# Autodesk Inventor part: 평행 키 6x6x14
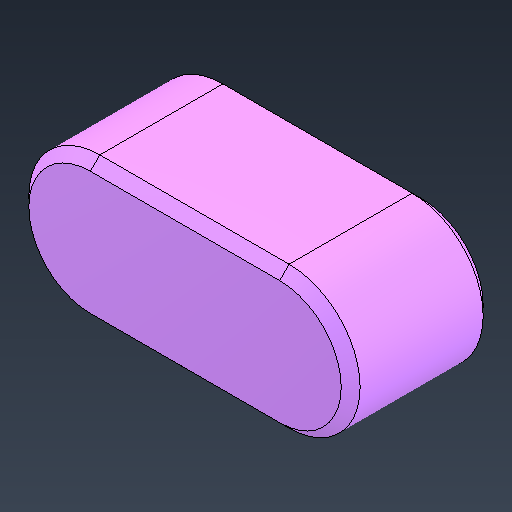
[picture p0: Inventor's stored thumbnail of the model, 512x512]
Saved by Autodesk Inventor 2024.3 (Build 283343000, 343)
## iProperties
Created: 2025-07
Part Number: 평행 키 6x6x14
Material: 강철, 연강
Description: 키 및 해당 키홈
Document SubType Name: Modeling
Designer: user
Density: 7.85 g/cm^3
Appearance: 기본값
Sending System: Autodesk Inventor 2026
Preprocessor: ST-DEVELOPER v20.1
Author: jhkim
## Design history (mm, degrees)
feature "Solid1"
node "솔리드1"
